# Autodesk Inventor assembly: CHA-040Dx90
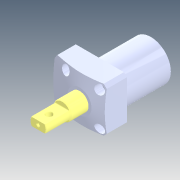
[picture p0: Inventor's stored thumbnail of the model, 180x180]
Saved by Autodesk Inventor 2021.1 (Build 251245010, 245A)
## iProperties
Created: 2018-07
Part Number: CHA-040Dx90
Description: STEP AP214
Document SubType Name: Assembly
Designer: user
Title: CHA-040Dx90(Ë«±Û£©.STEP
Revision Number: ÈÎºÎ
Sending System: SolidWorks 2016
Preprocessor: SwSTEP 2.0
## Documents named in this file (3)
- D:\Vault_2016\Projekty\Clamptek\Hydraulic\CHA\CHA\CHA-040\Inventor\CHA-040Dx90\CHA-040Dx90.iam
- D:\Vault_2016\Projekty\Clamptek\Hydraulic\CHA\CHA\CHA-040\Inventor\CHA-040Dx90\CHA-040±¾Ìå.ipt
- D:\Vault_2016\Projekty\Clamptek\Hydraulic\CHA\CHA\CHA-040\Inventor\CHA-040Dx90\CHA-040D(Ë«±Û£©»îÈû¸Ë.ipt
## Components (2 placed, 2 different names)
1. CHA-040±¾Ìå_1
2. CHA-040D(Ë«±Û£©»îÈû¸Ë_2
